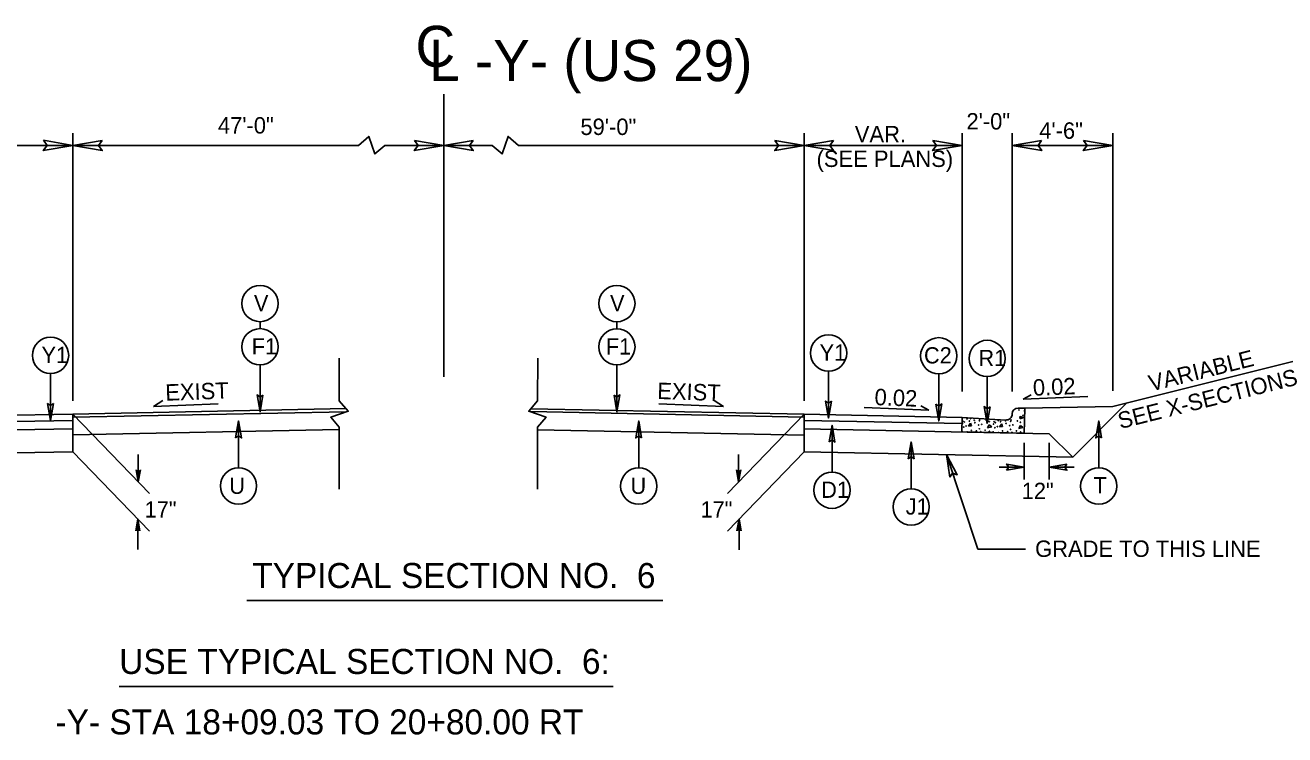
# Model space of a CAD drawing. Extents: x 1901582 to 1902252, y 193723 to 194156.
# Drawn here: x 1902014.5 to 1902064.9, y 193903.6 to 193932 of the extents above; entities that cross this region are included whole.
import ezdxf

# ---------------------------------------------------------------- set-up
doc = ezdxf.new("R2010")
doc.units = 0
for name, color, linetype in [('Default', 7, 'Continuous'), ('Old_Level_1', 7, 'Continuous'), ('Old_Level_11', 7, 'Continuous'), ('Old_Level_2', 7, 'Continuous'), ('Old_Level_20', 7, 'Continuous'), ('Prop Dimension', 7, 'Continuous'), ('Prop Terminator CELL', 7, 'Continuous'), ('Typical Curb CELL', 7, 'Continuous'), ('Typical Pavement Slope Information CELL', 7, 'Continuous'), ('Typical Terminator CELL', 7, 'Continuous'), ('Typical Text Asphalt at Bridge Approach CELL', 7, 'Continuous'), ('Typical Text Centerline CELL', 7, 'Continuous')]:
    doc.layers.add(name, color=color, linetype=linetype)

# ---------------------------------------------------------------- blocks, each defined once
blk = doc.blocks.new('TERMINATOR')
at = {"layer": 'Typical Terminator CELL'}
blk.add_lwpolyline([(-0.469, 0.081), (0, 0), (-0.471, -0.083), (-0.411, 0)], close=True, dxfattribs=at)

msp = doc.modelspace()

# ---------------------------------------------------------------- linework, layer by layer
at = {"layer": 'Default'}
for p, q in [((1902054.464, 193913.841), (1902054.464, 193915.312)), ((1902055.464, 193913.841), (1902055.464, 193915.312)), ((1902054.464, 193914.341), (1902053.464, 193914.341)), ((1902056.464, 193914.341), (1902055.464, 193914.341))]:
    msp.add_line(p, q, dxfattribs=at)
at = {"layer": 'Old_Level_1'}
for p, q in [((1902051.986, 193917.358), (1902051.986, 193927.692)), ((1902053.986, 193917.358), (1902053.986, 193927.692)), ((1902058.003, 193917.391), (1902058.003, 193927.692)), ((1902053.986, 193927.197), (1902058.003, 193927.197)), ((1902058.003, 193916.768), (1902065.307, 193918.594)), ((1902054.416, 193917.059), (1902054.746, 193917.233)), ((1902048.069, 193916.721), (1902050.655, 193916.619)), ((1902050.655, 193916.619), (1902050.325, 193916.792)), ((1902057.002, 193917.161), (1902054.416, 193917.059)), ((1902058.003, 193916.768), (1902054.484, 193916.698)), ((1902058.567, 193916.909), (1902056.4, 193914.743)), ((1902016.418, 193916.209), (1902006.163, 193916.004)), ((1902016.418, 193916.459), (1902006.418, 193916.259)), ((1902016.418, 193916.459), (1902027.345, 193916.678)), ((1902016.418, 193916.333), (1902027.345, 193916.552)), ((1902016.418, 193916.459), (1902016.418, 193914.959)), ((1902016.418, 193916.459), (1902019.486, 193913.289)), ((1902045.663, 193916.458), (1902034.736, 193916.676)), ((1902045.663, 193916.344), (1902034.736, 193916.562)), ((1902045.662, 193916.458), (1902042.593, 193913.288)), ((1902045.662, 193914.958), (1902045.662, 193916.458)), ((1902045.662, 193916.458), (1902051.977, 193916.331)), ((1902045.662, 193916.208), (1902051.972, 193916.081)), ((1902016.418, 193915.876), (1902005.823, 193915.664)), ((1902016.418, 193915.626), (1902027.077, 193915.839)), ((1902045.663, 193915.624), (1902035.004, 193915.837)), ((1902045.662, 193915.874), (1902055.464, 193915.678)), ((1902055.464, 193915.678), (1902056.4, 193914.743)), ((1902016.418, 193914.959), (1902004.387, 193914.718)), ((1902016.418, 193914.959), (1902019.486, 193911.789)), ((1902019.037, 193914.841), (1902019.037, 193913.753)), ((1902045.663, 193914.957), (1902042.595, 193911.788)), ((1902043.042, 193914.84), (1902043.042, 193913.752)), ((1902045.663, 193914.957), (1902056.4, 193914.743)), ((1902051.35, 193914.844), (1902052.61, 193911.06)), ((1902019.037, 193913.753), (1902018.953, 193914.23)), ((1902018.964, 193914.221), (1902019.037, 193913.753)), ((1902019.037, 193913.753), (1902018.978, 193914.212)), ((1902018.99, 193914.204), (1902019.037, 193913.753)), ((1902019.037, 193913.753), (1902019.002, 193914.195)), ((1902019.013, 193914.186), (1902019.037, 193913.753)), ((1902019.037, 193913.753), (1902019.025, 193914.177)), ((1902019.037, 193913.753), (1902019.121, 193914.23)), ((1902019.037, 193913.753), (1902019.11, 193914.221)), ((1902019.098, 193914.212), (1902019.037, 193913.753)), ((1902019.037, 193913.753), (1902019.086, 193914.204)), ((1902019.073, 193914.195), (1902019.037, 193913.753)), ((1902019.037, 193913.753), (1902019.061, 193914.186)), ((1902019.049, 193914.177), (1902019.037, 193913.753)), ((1902043.042, 193913.752), (1902042.958, 193914.229)), ((1902043.042, 193913.752), (1902042.97, 193914.22)), ((1902042.982, 193914.211), (1902043.042, 193913.752)), ((1902043.042, 193913.752), (1902042.994, 193914.203)), ((1902043.006, 193914.194), (1902043.042, 193913.752)), ((1902043.042, 193913.752), (1902043.018, 193914.185)), ((1902043.03, 193914.176), (1902043.042, 193913.752)), ((1902043.042, 193913.752), (1902043.127, 193914.229)), ((1902043.115, 193914.22), (1902043.042, 193913.752)), ((1902043.042, 193913.752), (1902043.102, 193914.211)), ((1902043.09, 193914.203), (1902043.042, 193913.752)), ((1902043.042, 193913.752), (1902043.078, 193914.194)), ((1902043.066, 193914.185), (1902043.042, 193913.752)), ((1902043.042, 193913.752), (1902043.054, 193914.176)), ((1902019.037, 193914.168), (1902019.037, 193913.753)), ((1902043.042, 193914.167), (1902043.042, 193913.752)), ((1902019.021, 193912.27), (1902018.936, 193911.793)), ((1902019.021, 193912.27), (1902018.948, 193911.802)), ((1902018.961, 193911.811), (1902019.021, 193912.27)), ((1902019.021, 193912.27), (1902018.973, 193911.82)), ((1902018.985, 193911.828), (1902019.021, 193912.27)), ((1902019.021, 193912.27), (1902018.997, 193911.837)), ((1902019.009, 193911.846), (1902019.021, 193912.27)), ((1902019.021, 193912.27), (1902019.105, 193911.793)), ((1902019.093, 193911.802), (1902019.021, 193912.27)), ((1902019.021, 193912.27), (1902019.081, 193911.811)), ((1902019.069, 193911.82), (1902019.021, 193912.27)), ((1902019.021, 193912.27), (1902019.057, 193911.828)), ((1902019.045, 193911.837), (1902019.021, 193912.27)), ((1902019.021, 193912.27), (1902019.033, 193911.846)), ((1902019.021, 193912.27), (1902019.021, 193911.045)), ((1902043.061, 193912.269), (1902042.976, 193911.791)), ((1902042.988, 193911.801), (1902043.061, 193912.269)), ((1902043.061, 193912.269), (1902043, 193911.809)), ((1902043.012, 193911.819), (1902043.061, 193912.269)), ((1902043.061, 193912.269), (1902043.025, 193911.827)), ((1902043.037, 193911.835), (1902043.061, 193912.269)), ((1902043.061, 193912.269), (1902043.049, 193911.844)), ((1902043.061, 193912.269), (1902043.145, 193911.791)), ((1902043.072, 193911.844), (1902043.061, 193912.269)), ((1902043.061, 193912.269), (1902043.084, 193911.835)), ((1902043.096, 193911.827), (1902043.061, 193912.269)), ((1902043.061, 193912.269), (1902043.108, 193911.819)), ((1902043.12, 193911.809), (1902043.061, 193912.269)), ((1902043.061, 193912.269), (1902043.133, 193911.801)), ((1902043.061, 193912.269), (1902043.061, 193911.043)), ((1902054.519, 193911.06), (1902052.61, 193911.06))]:
    msp.add_line(p, q, dxfattribs=at)
at = {"layer": 'Old_Level_11'}
for p, q in [((1902031.254, 193917.955), (1902031.254, 193929.243)), ((1902023.906, 193920.153), (1902023.906, 193919.875)), ((1902038.176, 193920.152), (1902038.176, 193919.874)), ((1902023.906, 193918.425), (1902023.906, 193916.551)), ((1902038.176, 193918.423), (1902038.176, 193916.549)), ((1902015.53, 193918.083), (1902015.53, 193916.209)), ((1902046.641, 193918.177), (1902046.641, 193916.303)), ((1902051.044, 193918.065), (1902051.044, 193916.191)), ((1902052.98, 193917.96), (1902052.98, 193916.086)), ((1902023.047, 193914.313), (1902023.047, 193916.187)), ((1902039.048, 193914.311), (1902039.048, 193916.186)), ((1902057.442, 193914.311), (1902057.442, 193916.185)), ((1902046.777, 193914.143), (1902046.777, 193916.017)), ((1902049.941, 193913.475), (1902049.941, 193915.349)), ((1902023.385, 193909.016), (1902040.01, 193909.016)), ((1902018.276, 193905.582), (1902038.02, 193905.582))]:
    msp.add_line(p, q, dxfattribs=at)
for points in [[(1902024.021, 193917.222), (1902023.906, 193916.551), (1902023.786, 193917.226), (1902023.906, 193917.14)], [(1902038.06, 193917.221), (1902038.176, 193916.549), (1902038.295, 193917.224), (1902038.176, 193917.138)], [(1902015.646, 193916.881), (1902015.53, 193916.209), (1902015.411, 193916.884), (1902015.53, 193916.799)], [(1902046.756, 193916.975), (1902046.641, 193916.303), (1902046.521, 193916.978), (1902046.641, 193916.892)], [(1902050.928, 193916.863), (1902051.044, 193916.191), (1902051.163, 193916.866), (1902051.044, 193916.781)], [(1902053.095, 193916.757), (1902052.98, 193916.086), (1902052.86, 193916.761), (1902052.98, 193916.675)], [(1902022.931, 193915.515), (1902023.047, 193916.187), (1902023.166, 193915.512), (1902023.047, 193915.597)], [(1902039.164, 193915.514), (1902039.048, 193916.186), (1902038.929, 193915.51), (1902039.048, 193915.596)], [(1902057.558, 193915.514), (1902057.442, 193916.185), (1902057.323, 193915.51), (1902057.442, 193915.596)], [(1902046.661, 193915.346), (1902046.777, 193916.017), (1902046.896, 193915.342), (1902046.777, 193915.428)], [(1902049.825, 193914.678), (1902049.941, 193915.349), (1902050.06, 193914.674), (1902049.941, 193914.76)]]:
    msp.add_lwpolyline(points, close=True, dxfattribs=at)
for centre in [(1902023.906, 193920.878), (1902038.176, 193920.877), (1902023.906, 193919.15), (1902038.176, 193919.148), (1902015.53, 193918.809), (1902046.641, 193918.902), (1902051.044, 193918.791), (1902052.98, 193918.685), (1902023.047, 193913.588), (1902039.048, 193913.586), (1902057.442, 193913.586), (1902046.777, 193913.418), (1902049.941, 193912.75)]:
    msp.add_circle(centre, 0.725, dxfattribs=at)
at = {"layer": 'Prop Dimension'}
for p, q in [((1902016.418, 193916.989), (1902016.418, 193927.693)), ((1902045.663, 193916.987), (1902045.664, 193927.692)), ((1902006.418, 193927.199), (1902016.418, 193927.199)), ((1902045.664, 193927.197), (1902051.986, 193927.197))]:
    msp.add_line(p, q, dxfattribs=at)
for points in [[(1902031.254, 193927.198), (1902028.895, 193927.198), (1902028.497, 193926.857), (1902028.256, 193927.554), (1902027.842, 193927.199), (1902016.418, 193927.198)], [(1902031.254, 193927.198), (1902033.187, 193927.198), (1902033.584, 193926.857), (1902033.826, 193927.554), (1902034.239, 193927.199), (1902045.664, 193927.198)]]:
    msp.add_lwpolyline(points, dxfattribs=at)
at = {"layer": 'Prop Terminator CELL'}
msp.add_lwpolyline([(1902051.487, 193913.941), (1902051.35, 193914.844), (1902051.787, 193914.036), (1902051.599, 193914.094)], close=True, dxfattribs=at)
at = {"layer": 'Typical Curb CELL'}
for p, q in [((1902054.484, 193916.698), (1902054.224, 193916.703)), ((1902054.464, 193915.698), (1902054.484, 193916.698)), ((1902051.965, 193915.748), (1902051.977, 193916.331)), ((1902051.977, 193916.331), (1902053.725, 193916.224)), ((1902053.98, 193916.458), (1902053.98, 193916.469)), ((1902054.287, 193916.369), (1902054.302, 193916.278)), ((1902054.44, 193916.321), (1902054.287, 193916.369)), ((1902054.302, 193916.278), (1902054.44, 193916.321)), ((1902054.464, 193915.698), (1902051.965, 193915.748)), ((1902052.23, 193915.983), (1902052.319, 193916.101)), ((1902052.351, 193915.986), (1902052.23, 193915.983)), ((1902052.319, 193916.101), (1902052.351, 193915.986)), ((1902052.995, 193915.916), (1902053.06, 193916.03)), ((1902053.161, 193915.953), (1902052.995, 193915.916)), ((1902053.06, 193916.03), (1902053.161, 193915.953)), ((1902053.48, 193915.958), (1902053.568, 193916.076)), ((1902053.6, 193915.961), (1902053.48, 193915.958)), ((1902053.568, 193916.076), (1902053.6, 193915.961)), ((1902054.243, 193915.891), (1902054.308, 193916.005)), ((1902054.41, 193915.928), (1902054.243, 193915.891)), ((1902054.308, 193916.005), (1902054.41, 193915.928))]:
    msp.add_line(p, q, dxfattribs=at)
for centre in [(1902052.008, 193916.182), (1902052.174, 193916.269), (1902052.269, 193916.182), (1902052.317, 193916.283), (1902052.464, 193916.217), (1902052.669, 193916.197), (1902052.687, 193916.247), (1902052.944, 193916.213), (1902053.422, 193916.202), (1902053.713, 193916.192), (1902053.936, 193916.222), (1902054.192, 193916.188), (1902054.253, 193916.627), (1902054.414, 193916.407), (1902054.469, 193916.588), (1902051.977, 193915.777), (1902051.989, 193916.085), (1902052.043, 193915.941), (1902052.063, 193916.146), (1902052.14, 193915.985), (1902052.186, 193915.75), (1902052.348, 193915.815), (1902052.491, 193916.115), (1902052.553, 193915.788), (1902052.637, 193916.026), (1902052.668, 193915.872), (1902052.723, 193915.756), (1902052.764, 193916.052), (1902052.901, 193915.815), (1902053.062, 193916.16), (1902053.072, 193915.772), (1902053.226, 193915.752), (1902053.237, 193916.06), (1902053.256, 193916.157), (1902053.292, 193915.916), (1902053.312, 193916.121), (1902053.389, 193915.96), (1902053.435, 193915.725), (1902053.518, 193916.157), (1902053.596, 193915.79), (1902053.739, 193916.09), (1902053.801, 193915.763), (1902053.886, 193916.001), (1902053.917, 193915.847), (1902053.918, 193916.172), (1902053.972, 193915.731), (1902054.012, 193916.027), (1902054.15, 193915.791), (1902054.311, 193916.135), (1902054.321, 193915.747)]:
    msp.add_circle(centre, 0.00802, dxfattribs=at)
for centre, start, end in [((1902054.219, 193916.464), 88.8542, 178.8542), ((1902053.74, 193916.463), 266.4698, 358.8542)]:
    msp.add_arc(centre, 0.24, start, end, dxfattribs=at)
at = {"layer": 'Typical Pavement Slope Information CELL'}
for p, q in [((1902019.646, 193916.771), (1902020.018, 193917.005)), ((1902019.646, 193916.771), (1902022.234, 193916.871)), ((1902042.435, 193916.769), (1902039.848, 193916.87)), ((1902042.435, 193916.769), (1902042.064, 193917.003))]:
    msp.add_line(p, q, dxfattribs=at)
at = {"layer": 'Typical Terminator CELL'}
for points in [[(1902015.246, 193927.401), (1902016.418, 193927.199), (1902015.239, 193926.991), (1902015.389, 193927.199)], [(1902017.589, 193927.4), (1902016.418, 193927.198), (1902017.596, 193926.99), (1902017.446, 193927.198)], [(1902030.082, 193927.4), (1902031.254, 193927.198), (1902030.076, 193926.99), (1902030.225, 193927.198)], [(1902032.426, 193927.4), (1902031.254, 193927.198), (1902032.432, 193926.99), (1902032.282, 193927.198)], [(1902044.492, 193927.398), (1902045.664, 193927.197), (1902044.485, 193926.988), (1902044.635, 193927.197)], [(1902046.835, 193927.399), (1902045.664, 193927.197), (1902046.842, 193926.989), (1902046.692, 193927.197)], [(1902050.805, 193927.399), (1902051.977, 193927.197), (1902050.799, 193926.989), (1902050.949, 193927.197)], [(1902055.157, 193927.399), (1902053.986, 193927.197), (1902055.164, 193926.989), (1902055.014, 193927.197)], [(1902056.831, 193927.399), (1902058.003, 193927.197), (1902056.824, 193926.989), (1902056.974, 193927.197)]]:
    msp.add_lwpolyline(points, close=True, dxfattribs=at)
at = {"layer": 'Typical Text Asphalt at Bridge Approach CELL'}
for points in [[(1902027.077, 193913.463), (1902027.077, 193915.937), (1902026.736, 193916.334), (1902027.432, 193916.576), (1902027.077, 193916.989), (1902027.073, 193918.692)], [(1902035.004, 193913.461), (1902035.004, 193915.936), (1902035.346, 193916.333), (1902034.65, 193916.575), (1902035.004, 193916.988), (1902035.008, 193918.69)]]:
    msp.add_lwpolyline(points, dxfattribs=at)

# ---------------------------------------------------------------- block references
at = {"layer": 'Old_Level_1', "xscale": 1.5, "yscale": -1.5}
msp.add_blockref('TERMINATOR', (1902054.464, 193914.341), dxfattribs=at)
at = {"layer": 'Old_Level_1', "xscale": 1.5, "yscale": -1.5, "rotation": -180}
msp.add_blockref('TERMINATOR', (1902055.464, 193914.341), dxfattribs=at)

# ---------------------------------------------------------------- texts
at = {"layer": 'Old_Level_1'}
for s, p in [('47\'-0"', (1902022.222, 193927.672)), ('59\'-0"', (1902036.717, 193927.613)), ('2\'-0"', (1902052.153, 193927.834)), ('VAR.', (1902047.689, 193927.32)), ('4\'-6"', (1902055.063, 193927.464)), ('(SEE PLANS)', (1902046.16, 193926.336)), ('GRADE TO THIS LINE', (1902054.897, 193910.753))]:
    msp.add_text(s, height=0.656, dxfattribs=at).set_placement(p)
for s, p in [('VARIABLE', (1902059.533, 193917.36)), ('SEE X-SECTIONS', (1902058.302, 193915.861))]:
    msp.add_text(s, height=0.656, rotation=14.0362, dxfattribs=at).set_placement(p)
at = {"layer": 'Old_Level_11'}
for s, p in [('TYPICAL SECTION NO.  6', (1902023.595, 193909.51)), ('USE TYPICAL SECTION NO.  6:', (1902018.276, 193906.076)), ('-Y- STA 18+09.03 TO 20+80.00 RT', (1902015.729, 193903.66))]:
    msp.add_text(s, height=1, dxfattribs=at).set_placement(p)
at = {"layer": 'Old_Level_2'}
for s, rotation, p in [('EXIST', 1.9721, (1902020.129, 193916.994)), ('EXIST', 358.0279, (1902039.782, 193917.067)), ('0.02', 2.2539, (1902054.822, 193917.192)), ('0.02', 357.7461, (1902048.468, 193916.822))]:
    msp.add_text(s, height=0.656, rotation=rotation, dxfattribs=at).set_placement(p)
at = {"layer": 'Old_Level_20'}
for s, height, p in [('V', 0.649, (1902023.663, 193920.572)), ('V', 0.649, (1902037.902, 193920.571)), ('F1', 0.6491, (1902023.574, 193918.844)), ('F1', 0.6491, (1902037.734, 193918.842)), ('Y1', 0.6491, (1902046.281, 193918.596)), ('Y1', 0.6491, (1902015.17, 193918.502)), ('C2', 0.6491, (1902050.455, 193918.484)), ('R1', 0.6491, (1902052.633, 193918.379)), ('U', 0.649, (1902022.675, 193913.273)), ('U', 0.649, (1902038.72, 193913.272)), ('D1', 0.6491, (1902046.344, 193913.114)), ('12"', 0.6491, (1902054.365, 193913.069)), ('T', 0.649, (1902057.231, 193913.293)), ('17"', 0.6491, (1902019.294, 193912.327)), ('17"', 0.6491, (1902041.52, 193912.326)), ('J1', 0.6491, (1902049.723, 193912.446))]:
    msp.add_text(s, height=height, dxfattribs=at).set_placement(p)
at = {"layer": 'Typical Text Centerline CELL'}
msp.add_text('C', height=1.64, dxfattribs=at).set_placement((1902030.123, 193930.337))
msp.add_text('L -Y- (US 29)', height=1.64109, rotation=359.9469, dxfattribs=at).set_placement((1902030.668, 193929.776))

doc.saveas('drawing.dxf')
